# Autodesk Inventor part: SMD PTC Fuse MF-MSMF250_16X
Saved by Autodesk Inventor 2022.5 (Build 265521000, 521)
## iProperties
Created: 2024-12
Part Number: SMD PTC Fuse MF-MSMF250_16X
Material: Generic
Document SubType Name: Modeling
Designer: AdminForWorker
Density: 1 g/cm^3
Appearance: Default
Title: SMD PTC Fuse MF-MSMF250_16X v1
Author: AdminForWorker
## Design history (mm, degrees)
feature "Body2"
feature "Body3"
feature "Body5"
feature "Body6"
feature "Body7"
body "Solid1"
body "Solid2"
body "Solid3"
body "Solid4"
body "Solid5"
